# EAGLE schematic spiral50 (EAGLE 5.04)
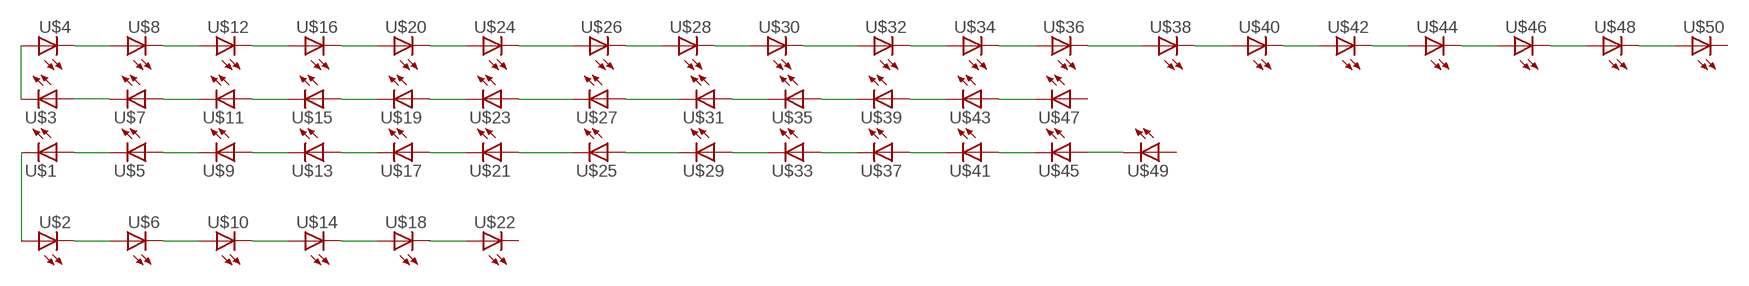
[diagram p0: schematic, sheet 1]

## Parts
U$1  LED5MM  [LED5MM]
U$2  LED5MM  [LED5MM]
U$3  LED5MM  [LED5MM]
U$4  LED5MM  [LED5MM]
U$5  LED5MM  [LED5MM]
U$6  LED5MM  [LED5MM]
U$7  LED5MM  [LED5MM]
U$8  LED5MM  [LED5MM]
U$9  LED5MM  [LED5MM]
U$10  LED5MM  [LED5MM]
U$11  LED5MM  [LED5MM]
U$12  LED5MM  [LED5MM]
U$13  LED5MM  [LED5MM]
U$14  LED5MM  [LED5MM]
U$15  LED5MM  [LED5MM]
U$16  LED5MM  [LED5MM]
U$17  LED5MM  [LED5MM]
U$18  LED5MM  [LED5MM]
U$19  LED5MM  [LED5MM]
U$20  LED5MM  [LED5MM]
U$21  LED5MM  [LED5MM]
U$22  LED5MM  [LED5MM]
U$23  LED5MM  [LED5MM]
U$24  LED5MM  [LED5MM]
U$25  LED5MM  [LED5MM]
U$26  LED5MM  [LED5MM]
U$27  LED5MM  [LED5MM]
U$28  LED5MM  [LED5MM]
U$29  LED5MM  [LED5MM]
U$30  LED5MM  [LED5MM]
U$31  LED5MM  [LED5MM]
U$32  LED5MM  [LED5MM]
U$33  LED5MM  [LED5MM]
U$34  LED5MM  [LED5MM]
U$35  LED5MM  [LED5MM]
U$36  LED5MM  [LED5MM]
U$37  LED5MM  [LED5MM]
U$38  LED5MM  [LED5MM]
U$39  LED5MM  [LED5MM]
U$40  LED5MM  [LED5MM]
U$41  LED5MM  [LED5MM]
U$42  LED5MM  [LED5MM]
U$43  LED5MM  [LED5MM]
U$44  LED5MM  [LED5MM]
U$45  LED5MM  [LED5MM]
U$46  LED5MM  [LED5MM]
U$47  LED5MM  [LED5MM]
U$48  LED5MM  [LED5MM]
U$49  LED5MM  [LED5MM]
U$50  LED5MM  [LED5MM]

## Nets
N$1: U$1.A U$5.K(C)
N$2: U$3.A U$7.K(C)
N$3: U$5.A U$9.K(C)
N$4: U$7.A U$11.K(C)
N$5: U$11.A U$15.K(C)
N$6: U$15.A U$19.K(C)
N$7: U$19.A U$23.K(C)
N$8: U$23.A U$27.K(C)
N$9: U$27.A U$31.K(C)
N$10: U$9.A U$13.K(C)
N$11: U$13.A U$17.K(C)
N$12: U$17.A U$21.K(C)
N$13: U$21.A U$25.K(C)
N$14: U$25.A U$29.K(C)
N$15: U$31.A U$35.K(C)
N$16: U$35.A U$39.K(C)
N$17: U$39.A U$43.K(C)
N$18: U$43.A U$47.K(C)
N$19: U$29.A U$33.K(C)
N$20: U$33.A U$37.K(C)
N$21: U$37.A U$41.K(C)
N$22: U$41.A U$45.K(C)
N$23: U$1.K(C) U$2.A
N$24: U$2.K(C) U$6.A
N$25: U$45.A U$49.K(C)
N$26: U$6.K(C) U$10.A
N$27: U$10.K(C) U$14.A
N$28: U$14.K(C) U$18.A
N$29: U$18.K(C) U$22.A
N$30: U$4.K(C) U$8.A
N$31: U$8.K(C) U$12.A
N$32: U$12.K(C) U$16.A
N$33: U$16.K(C) U$20.A
N$34: U$20.K(C) U$24.A
N$35: U$24.K(C) U$26.A
N$36: U$26.K(C) U$28.A
N$37: U$28.K(C) U$30.A
N$38: U$30.K(C) U$32.A
N$39: U$32.K(C) U$34.A
N$40: U$3.K(C) U$4.A
N$41: U$34.K(C) U$36.A
N$42: U$36.K(C) U$38.A
N$43: U$38.K(C) U$40.A
N$44: U$40.K(C) U$42.A
N$45: U$42.K(C) U$44.A
N$46: U$44.K(C) U$46.A
N$47: U$46.K(C) U$48.A
N$48: U$48.K(C) U$50.A
Unconnected: U$22.K(C) U$47.A U$49.A U$50.K(C)

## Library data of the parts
U$1-U$50 = led(2):LED: LED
